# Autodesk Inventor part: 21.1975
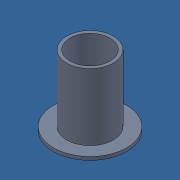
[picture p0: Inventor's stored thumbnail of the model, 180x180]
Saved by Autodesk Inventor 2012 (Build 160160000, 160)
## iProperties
Created: 2011-09
Part Number: 21.1975
Document SubType Name: Modeling
Designer: Administrator
Density: 1.4 g/cm^3
Mass: 0.189674 g
Surface Area: 5.68628 cm^2
Volume: 0.135481 cm^3
Material: PVC-U
Description: PLASTIC 6mm BUSHING
Vendor: S
Author: Administrator
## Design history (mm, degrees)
feature "Base1"
body "Solid1"
